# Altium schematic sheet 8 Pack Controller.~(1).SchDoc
size B; PageSetup: Record=PageOptions|CenterHorizontal=True|CenterVertical=True|PrintScale=1.09|XCorrection=1.00|YCorrection=1.00|PrintKind=0|BorderSize=5000000|LeftOffset=0|BottomOffset=0|Orientation=2|PaperLength=1000|PaperWidth=1000|Scale=100|PaperSource=15|PrintQuality=600|MediaType=1|DitherType=10|PaperKind=11x17|PrintScaleMode=1
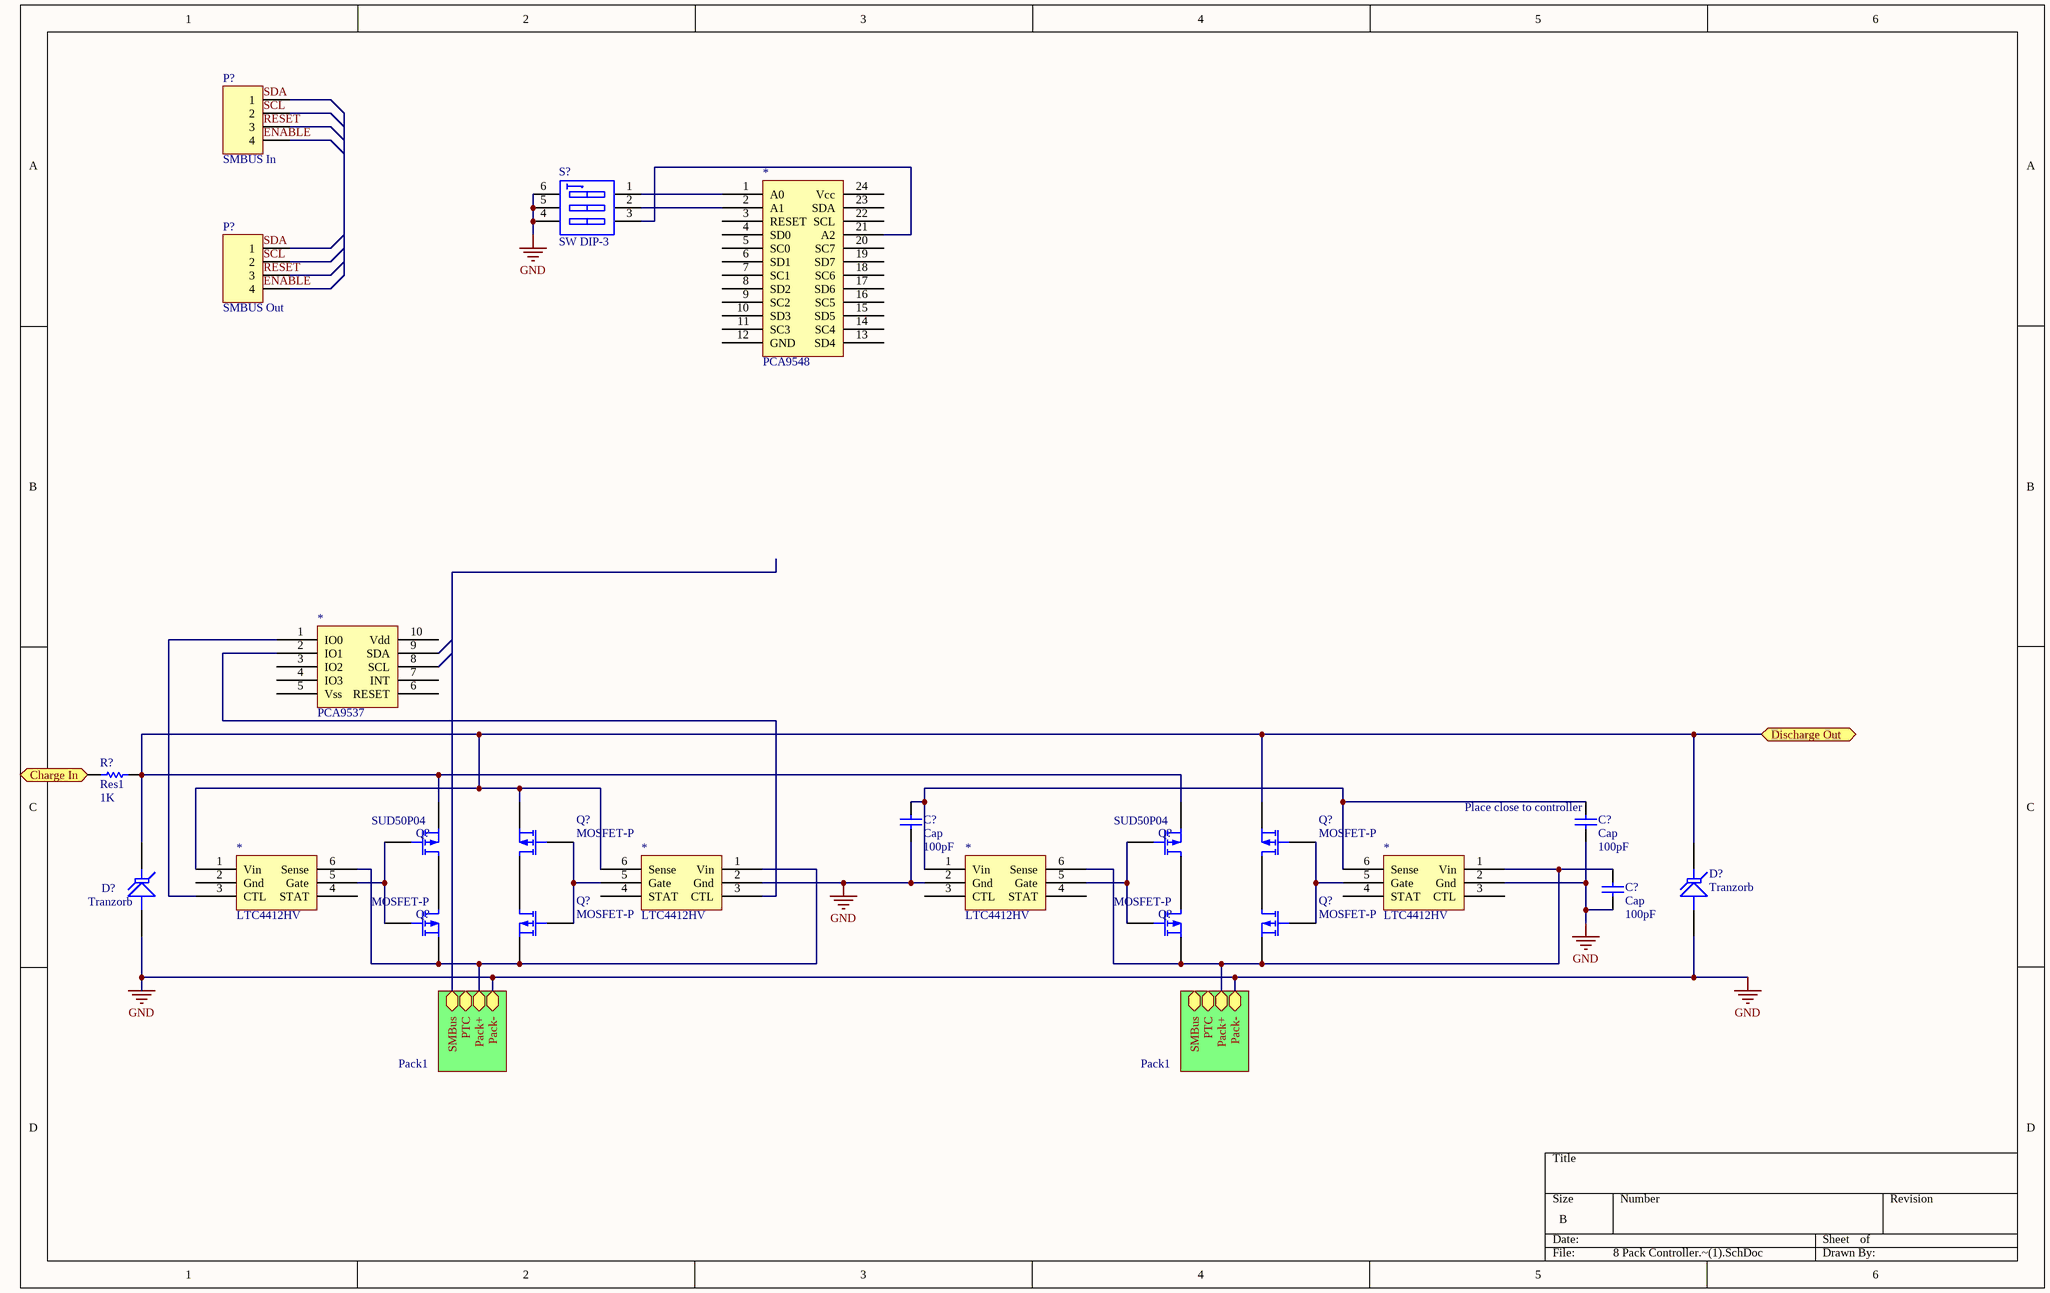
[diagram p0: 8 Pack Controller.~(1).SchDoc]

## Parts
(Parts that share a designator on the sheet are numbered #1, #2 ... from top to bottom, then left to right.)
*#1  PCA9548
*#2  PCA9537
*#3  LTC4412HV
*#4  LTC4412HV
*#5  LTC4412HV
*#6  LTC4412HV
C?#1  Cap  value 100pF  [RAD-0.3]
C?#2  Cap  value 100pF  [RAD-0.3]
C?#3  Cap  value 100pF  [RAD-0.3]
D?#1  Tranzorb  [DIO10.2-7x2.7]
D?#2  Tranzorb  [DIO10.2-7x2.7]
P?#1  SMBUS In  [HDR1X4]
P?#2  SMBUS Out  [HDR1X4]
Q?#1  SUD50P04  [BCY-W3/B.8]
Q?#2  MOSFET-P  [BCY-W3/B.8]
Q?#3  SUD50P04  [BCY-W3/B.8]
Q?#4  MOSFET-P  [BCY-W3/B.8]
Q?#5  MOSFET-P  [BCY-W3/B.8]
Q?#6  MOSFET-P  [BCY-W3/B.8]
Q?#7  MOSFET-P  [BCY-W3/B.8]
Q?#8  MOSFET-P  [BCY-W3/B.8]
R?  Res1  value 1K  [AXIAL-0.3]
S?  SW DIP-3  [DIP-6]

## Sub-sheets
Pack1 = File Name: SMBus, PTC, Pack+, Pack-
Pack1 = File Name: SMBus, PTC, Pack+, Pack-

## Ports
Charge In, Discharge Out

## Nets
GND: *#4.2(Gnd) *#5.2(Gnd) *#6.2(Gnd) C?#1.1 C?#2.1 C?#3.1 D?#1.1(A) D?#2.1(A) S?.4(B3) S?.5(B2) S?.6(B1) ; sheet Pack1/Pack-, sheet Pack1/Pack-
Charge In: R?.1 ; port Charge In
Discharge Out: *#3.1(Vin) *#4.6(Sense) D?#1.2(K) D?#2.2(K) Q?#1.3(S) Q?#2.3(S) Q?#3.3(S) Q?#4.3(S) R?.2 ; port Discharge Out
Net*#1_1: *#1.1(A0) S?.1(A1)
Net*#1_2: *#1.2(A1) S?.2(A2)
Net*#1_21: *#1.21(A2) S?.3(A3)
Net*#2_1: *#2.1(IO0) *#3.3(CTL)
Net*#2_2: *#2.2(IO1) *#4.3(CTL)
Net*#3_5: *#3.5(Gate) Q?#1.2(G) Q?#5.2(G)
Net*#3_6: *#3.6(Sense) *#4.1(Vin) Q?#5.3(S) Q?#6.3(S) ; sheet Pack1/Pack+
Net*#4_5: *#4.5(Gate) Q?#2.2(G) Q?#6.2(G)
Net*#5_1: *#5.1(Vin) *#6.6(Sense) C?#1.2 C?#2.2
Net*#5_5: *#5.5(Gate) Q?#3.2(G) Q?#7.2(G)
Net*#5_6: *#5.6(Sense) *#6.1(Vin) C?#3.2 Q?#7.3(S) Q?#8.3(S) ; sheet Pack1/Pack+
Net*#6_5: *#6.5(Gate) Q?#4.2(G) Q?#8.2(G)
NetQ?#1_1: Q?#1.1(D) Q?#5.1(D)
NetQ?#2_1: Q?#2.1(D) Q?#6.1(D)
NetQ?#3_1: Q?#3.1(D) Q?#7.1(D)
NetQ?#4_1: Q?#4.1(D) Q?#8.1(D)

Not connected (* = marked no-connect by the designer): *#1 3(RESET) 4(SD0) 5(SC0) 6(SD1) 7(SC1) 8(SD2) 9(SC2) 10(SD3) 11(SC3) 12(GND) 13(SD4) 14(SC4) 15(SD5) 16(SC5) 17(SD6) 18(SC6) 19(SD7) 20(SC7) 22(SCL) 23(SDA) 24(Vcc); *#2 3(IO2) 4(IO3) 5(Vss) 6(RESET) 7(INT) 8(SCL) 9(SDA) 10(Vdd); *#3 2(Gnd) 4(STAT); *#4 4(STAT); *#5 3(CTL) 4(STAT); *#6 3(CTL) 4(STAT); P?#1 1 2 3 4; P?#2 1 2 3 4

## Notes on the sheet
- (near C?#2) Place close to controller
- Labels drawn without touching a wire or pin: ENABLE, RESET, SCL, SDA

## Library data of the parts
C?#1-C?#3 = Cap: Capacitor
P?#1 P?#2 = Header 4: Header, 4-Pin
Q?#1-Q?#8 = MOSFET-P: P-Channel MOSFET
R? = Res1: Resistor
S? = SW DIP-3: DIP Switch, 3 Position, SPST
